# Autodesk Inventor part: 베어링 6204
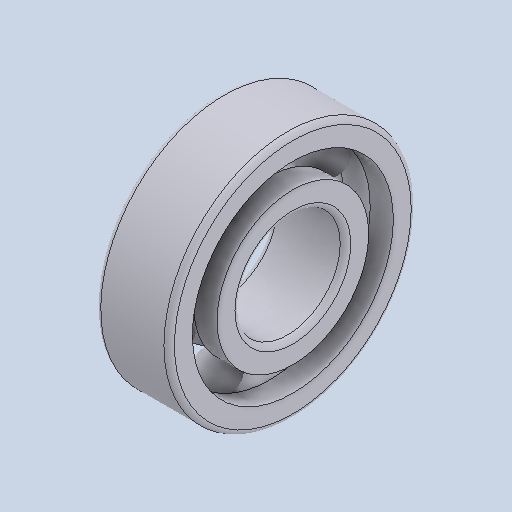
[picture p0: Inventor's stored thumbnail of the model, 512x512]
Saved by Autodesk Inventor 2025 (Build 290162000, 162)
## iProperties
Created: 2024-08
Part Number: 베어링 6204
Material: 강철, 연강
Description: 깊은 그루브 볼 베어링
Document SubType Name: Modeling
Designer: SAMSUNG
Density: 7.86 g/cm^3
Appearance: 기본값
Author: jhkim
Sending System: Autodesk Inventor 2025
Preprocessor: ST-DEVELOPER v20
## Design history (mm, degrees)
feature "Solid1"
feature "Solid1:1"
feature "Solid1:2"
feature "Solid1:3"
feature "Solid1:4"
feature "Solid1:5"
feature "Solid1:6"
feature "Solid1:7"
feature "Solid1:8"
node "솔리드1"
node "솔리드2"
node "솔리드3"
node "솔리드4"
node "솔리드5"
node "솔리드6"
node "솔리드7"
node "솔리드8"
node "솔리드9"
